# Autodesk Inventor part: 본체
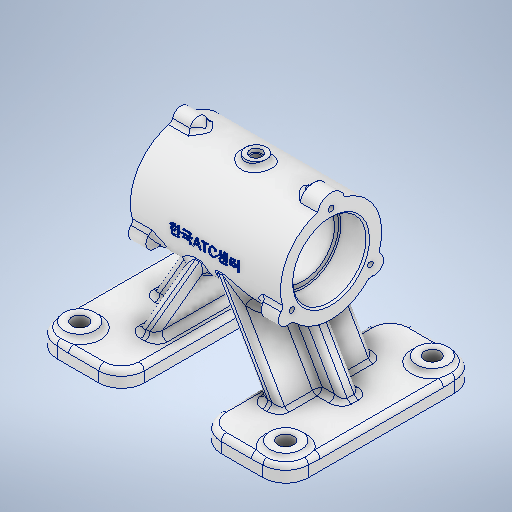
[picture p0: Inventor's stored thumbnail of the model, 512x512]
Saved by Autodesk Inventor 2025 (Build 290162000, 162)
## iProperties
Created: 2026-04
Part Number: 본체
Material: 알루미늄 6061
Document SubType Name: Modeling
Designer: KDI
Density: 2.7 g/cm^3
Appearance: 알루미늄 - 평지
Mass: 744.03 g
Surface Area: 671.494 cm^2
Volume: 275.567 cm^3
Author: KDI
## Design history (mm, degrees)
sketch "스케치1"
  geometry: L1 (-49.679, 0)-(37.321, 0); L2 (-43, 0)-(-43, 29); L3 (-43, 29)-(0, 29); L4 (-43, 21)-(-27.6, 21); L5 (-27, 20.4)-(-27, 18); L6 (-27, 18)-(0, 18); L7 (0, 0)-(0, 69.66); L8 (43, 0)-(43, 29); L9 (43, 29)-(0, 29); L10 (43, 21)-(27.6, 21); L11 (27, 20.4)-(27, 18); L12 (27, 18)-(0, 18); A1 r 0.6 centre (-27.6, 20.4) between (-27, 20.4) and (-27.6, 21); A2 r 0.6 centre (27.6, 20.4) between (27.6, 21) and (27, 20.4); 4 further points
  constraints: 24 end point, 7 point on line, 6 symmetric about line, 4 perpendicular, 4 point on circle, 4 tangent, 2 centre point, 2 vertical, 1 equal radius, 1 horizontal, 1 horizontal alignment, 1 midpoint
  dimensions: "d0" = 58 diameter of L3 L1; "d1" = 42 diameter of point (-35.3, 21) L1; "d2" = 36 diameter of L6 L1; "d3" = 43 distance between parallel lines of L7 L2; "d4" = 16 distance of L4.start point (-27, 21); "d77" = 0.6 radius of A1
revolve "회전1" sketch "스케치1" stored, may be unused: angle "d5" = 90 deg
sketch "스케치2"
  geometry: L1 (-43, -29)-(43, -29) reference; L2 (-30.845, -21)-(-55.094, -63); L3 (-55.094, -63)-(-72, -63); L4 (-72, -63)-(-72, -72); L5 (-72, -72)-(-22, -72); L6 (-22, -72)-(-22, -63); L7 (-22, -63)-(-32, -63); L8 (-32, -63)-(-7.751, -21); L9 (0, 47.304)-(0, -130.656); L10 (30.845, -21)-(55.094, -63); L11 (55.094, -63)-(72, -63); L12 (72, -63)-(72, -72); L13 (72, -72)-(22, -72); L14 (22, -72)-(22, -63); L15 (22, -63)-(32, -63); L16 (32, -63)-(7.751, -21); L17 (-55.094, -63)-(-32, -63); L18 (-16.989, -21)-(-42.392, -65); L19 (16.989, -21)-(42.392, -65); L20 (32, -63)-(55.094, -63); L21 (-43, -21)-(-43, 21) reference; L22 (43, -21)-(43, 21) reference; L23 (-43, -21)-(43, -21); L24 (-43, -21)-(43, -21); 18 further points
  constraints: 42 end point, 19 point on line, 10 symmetric about line, 3 horizontal, 3 parallel, 3 perpendicular, 1 vertical, 1 vertical alignment
  dimensions: "d6" = 50 distance of L4.end L5.end; "d7" = 10 distance of L6.end L7.end; "d8" = 9 distance of L5.end L6.end; "d9" = 44 distance between parallel lines of L14 L6; "d10" = 60 deg angle of L16 L8; "d11" = 72 distance from line of L5 point (0, 0); "d12" = 8 distance between parallel lines of L18 L8; "d13" = 12 distance between parallel lines of L18 L2; "d90" = 10 distance of L14.end L15.end (derived)
extrude "돌출1" join sketch "스케치2" stored distance "d14" = 110; taper "d15" = 0 deg
extrude "돌출2" join sketch "스케치2" stored distance "d16" = 10; taper "d17" = 0 deg
extrude "돌출3" join sketch "스케치2" stored distance "d18" = 54; taper "d19" = 0 deg
feature "면 삭제1"
feature "면 삭제2"
sketch "스케치7"
  geometry: C1 r 9 at (13, -13); C2 r 9 at (131, -13); C3 r 9 at (13, -97); C4 r 9 at (131, -97); C5 r 4.5 at (13, -13); C6 r 4.5 at (131, -13); C7 r 4.5 at (131, -97); C8 r 4.5 at (13, -97); 1 further point
  constraints: 8 centre point, 4 coincident, 3 equal radius, 2 horizontal alignment, 2 vertical alignment
  dimensions: "d20" = 18 diameter of C1; "d21" = 118 distance of C2.centre C1.centre; "d22" = 59 horizontal distance of point (72, -55) C1.centre (= 0.5 x d21); "d23" = 84 distance of C3.centre C1.centre; "d24" = 42 vertical distance of point (72, -55) C1.centre (= 0.5 x d23); "d25" = 9 diameter of C5; "d26" = 9 diameter of C6; "d27" = 9 diameter of C7; "d28" = 9 diameter of C8
extrude "돌출4" join sketch "스케치7" distance "d29" = 3; taper "d30" = 0 deg
extrude "돌출5" cut sketch "스케치7" extent not by distance; stored distance "d31" = 0; taper "d32" = 0 deg
node "작업 평면1"
sketch "스케치8"
  geometry: C1 r 6 at (0, 0); 1 further point
  constraints: 1 centre point, 1 coincident
  dimensions: "d34" = 12 diameter of C1
extrude "돌출6" join sketch "스케치8" stored distance "d35" = 3; taper "d36" = 0 deg
sketch "스케치10"
  geometry: L1 (-43, 29)-(43, 29) reference; L2 (43, 29)-(43, 34); L3 (43, 34)-(33, 34); L4 (33, 34)-(28, 29); L5 (-43, 29)-(-43, 34); L6 (-43, 34)-(-33, 34); L7 (-33, 34)-(-28, 29); L8 (72, -72)-(22, -72) reference; 1 further point
  constraints: 12 end point, 4 perpendicular, 3 point on line, 1 vertical
  dimensions: "d47" = 90 deg angle of L7 L4; "d48" = 10 distance of L2.end L3.end; "d49" = 10 distance of L5.end L6.end; "d50" = 106 distance between parallel lines of L8 L3
revolve "회전2" sketch "스케치10" stored, may be unused: angle "d51" = 360 deg
sketch "스케치11" dims "d55" = 52
  geometry: A1 r 29 centre (0, -29) between (27.232, -38.97) and (4.981, -0.431) reference; 3 further points
  constraints: 2 vertical alignment, 1 coincident, 2 other
hole "구멍1" sketch "스케치11" at (0, -3) diameter "d56" = 3.242; stored, may be unused: countersink angle "d60" = 90 deg, drill point angle "d62" = 118 deg; dims "d57" = 8, "d58" = 4, "d59" = 2, "d61" = 10
sketch "스케치12"
  geometry: 2 further points
  constraints: 1 coincident
hole "구멍2" sketch "스케치12" at (0, 0) diameter "d66" = 5.1881; stored, may be unused: countersink angle "d70" = 90 deg, drill point angle "d72" = 0 deg; dims "d67" = 20, "d68" = 7, "d69" = 2, "d71" = 10
fillet "모깎기1" dims "d73" = 13
sketch "스케치13"
  geometry: 3 further points
  constraints: 1 coincident, 1 other
  dimensions: "d74" = 72 horizontal distance of point (72, -72) point (0, 0)
feature "엠보싱1" sketch "스케치13" dims "d75" = 0.5, "d76" = 0
chamfer "모따기1" distance "d78" = 1; stored, may be unused: second distance "d79" = 2, angle "d80" = 45 deg
fillet "모깎기2" dims "d81" = 3
fillet "모깎기3" dims "d82" = 3
fillet "모깎기4" dims "d83" = 3
fillet "모깎기5" dims "d84" = 3
fillet "모깎기6" dims "d85" = 3
sketch "스케치14"
  geometry: L1 (-54.846, 34)-(73.75, 34); L2 (42, -72)-(-42, -72) reference; C1 r 8 at (0, 26); C2 r 22 at (0, 0) reference; A1 r 29 centre (0, 0) between (-7.008, 28.141) and (-27.874, -8.002) reference; A2 r 29 centre (0, 0) between (27.874, -8.002) and (7.008, 28.141) reference; 4 further points
  constraints: 2 end point, 1 centre point, 1 coincident, 1 horizontal, 1 tangent, 1 vertical alignment, 3 other
  dimensions: "d86" = 16 diameter of C1; "d87" = 106 distance between parallel lines of L2 L1
extrude "돌출9" join sketch "스케치14" distance "d88" = 10; taper "d89" = 0 deg
sketch "스케치15"
  geometry: L1 (43, 34)-(33, 34) reference; L2 (33, 34)-(25.311, 29); L3 (-26.757, 29)-(26.757, 29) reference; L4 (-26.757, 29)-(26.757, 29) reference; 2 further points; 1 other entity
  constraints: 2 end point, 2 point on line, 1 other
node "솔리드1"
mirror "미러1"
pattern_circular "원형 패턴1" dims angle "d53" = 360 deg
pattern_circular "원형 패턴2" dims angle "d64" = 360 deg
mirror "미러2"
mirror "미러3"
feature "A9D066F2-1C7D-4E18-AEED-F7BC21143FA4" dims "d66" = 5.1881, "d67" = 20, "d68" = 7, "d69" = 2, "d70" = 90 deg, "d71" = 10, "d72" = 0
other parameters: "d33" = 32
